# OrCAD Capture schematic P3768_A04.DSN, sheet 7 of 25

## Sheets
7 0018_CAMERA: size Custom
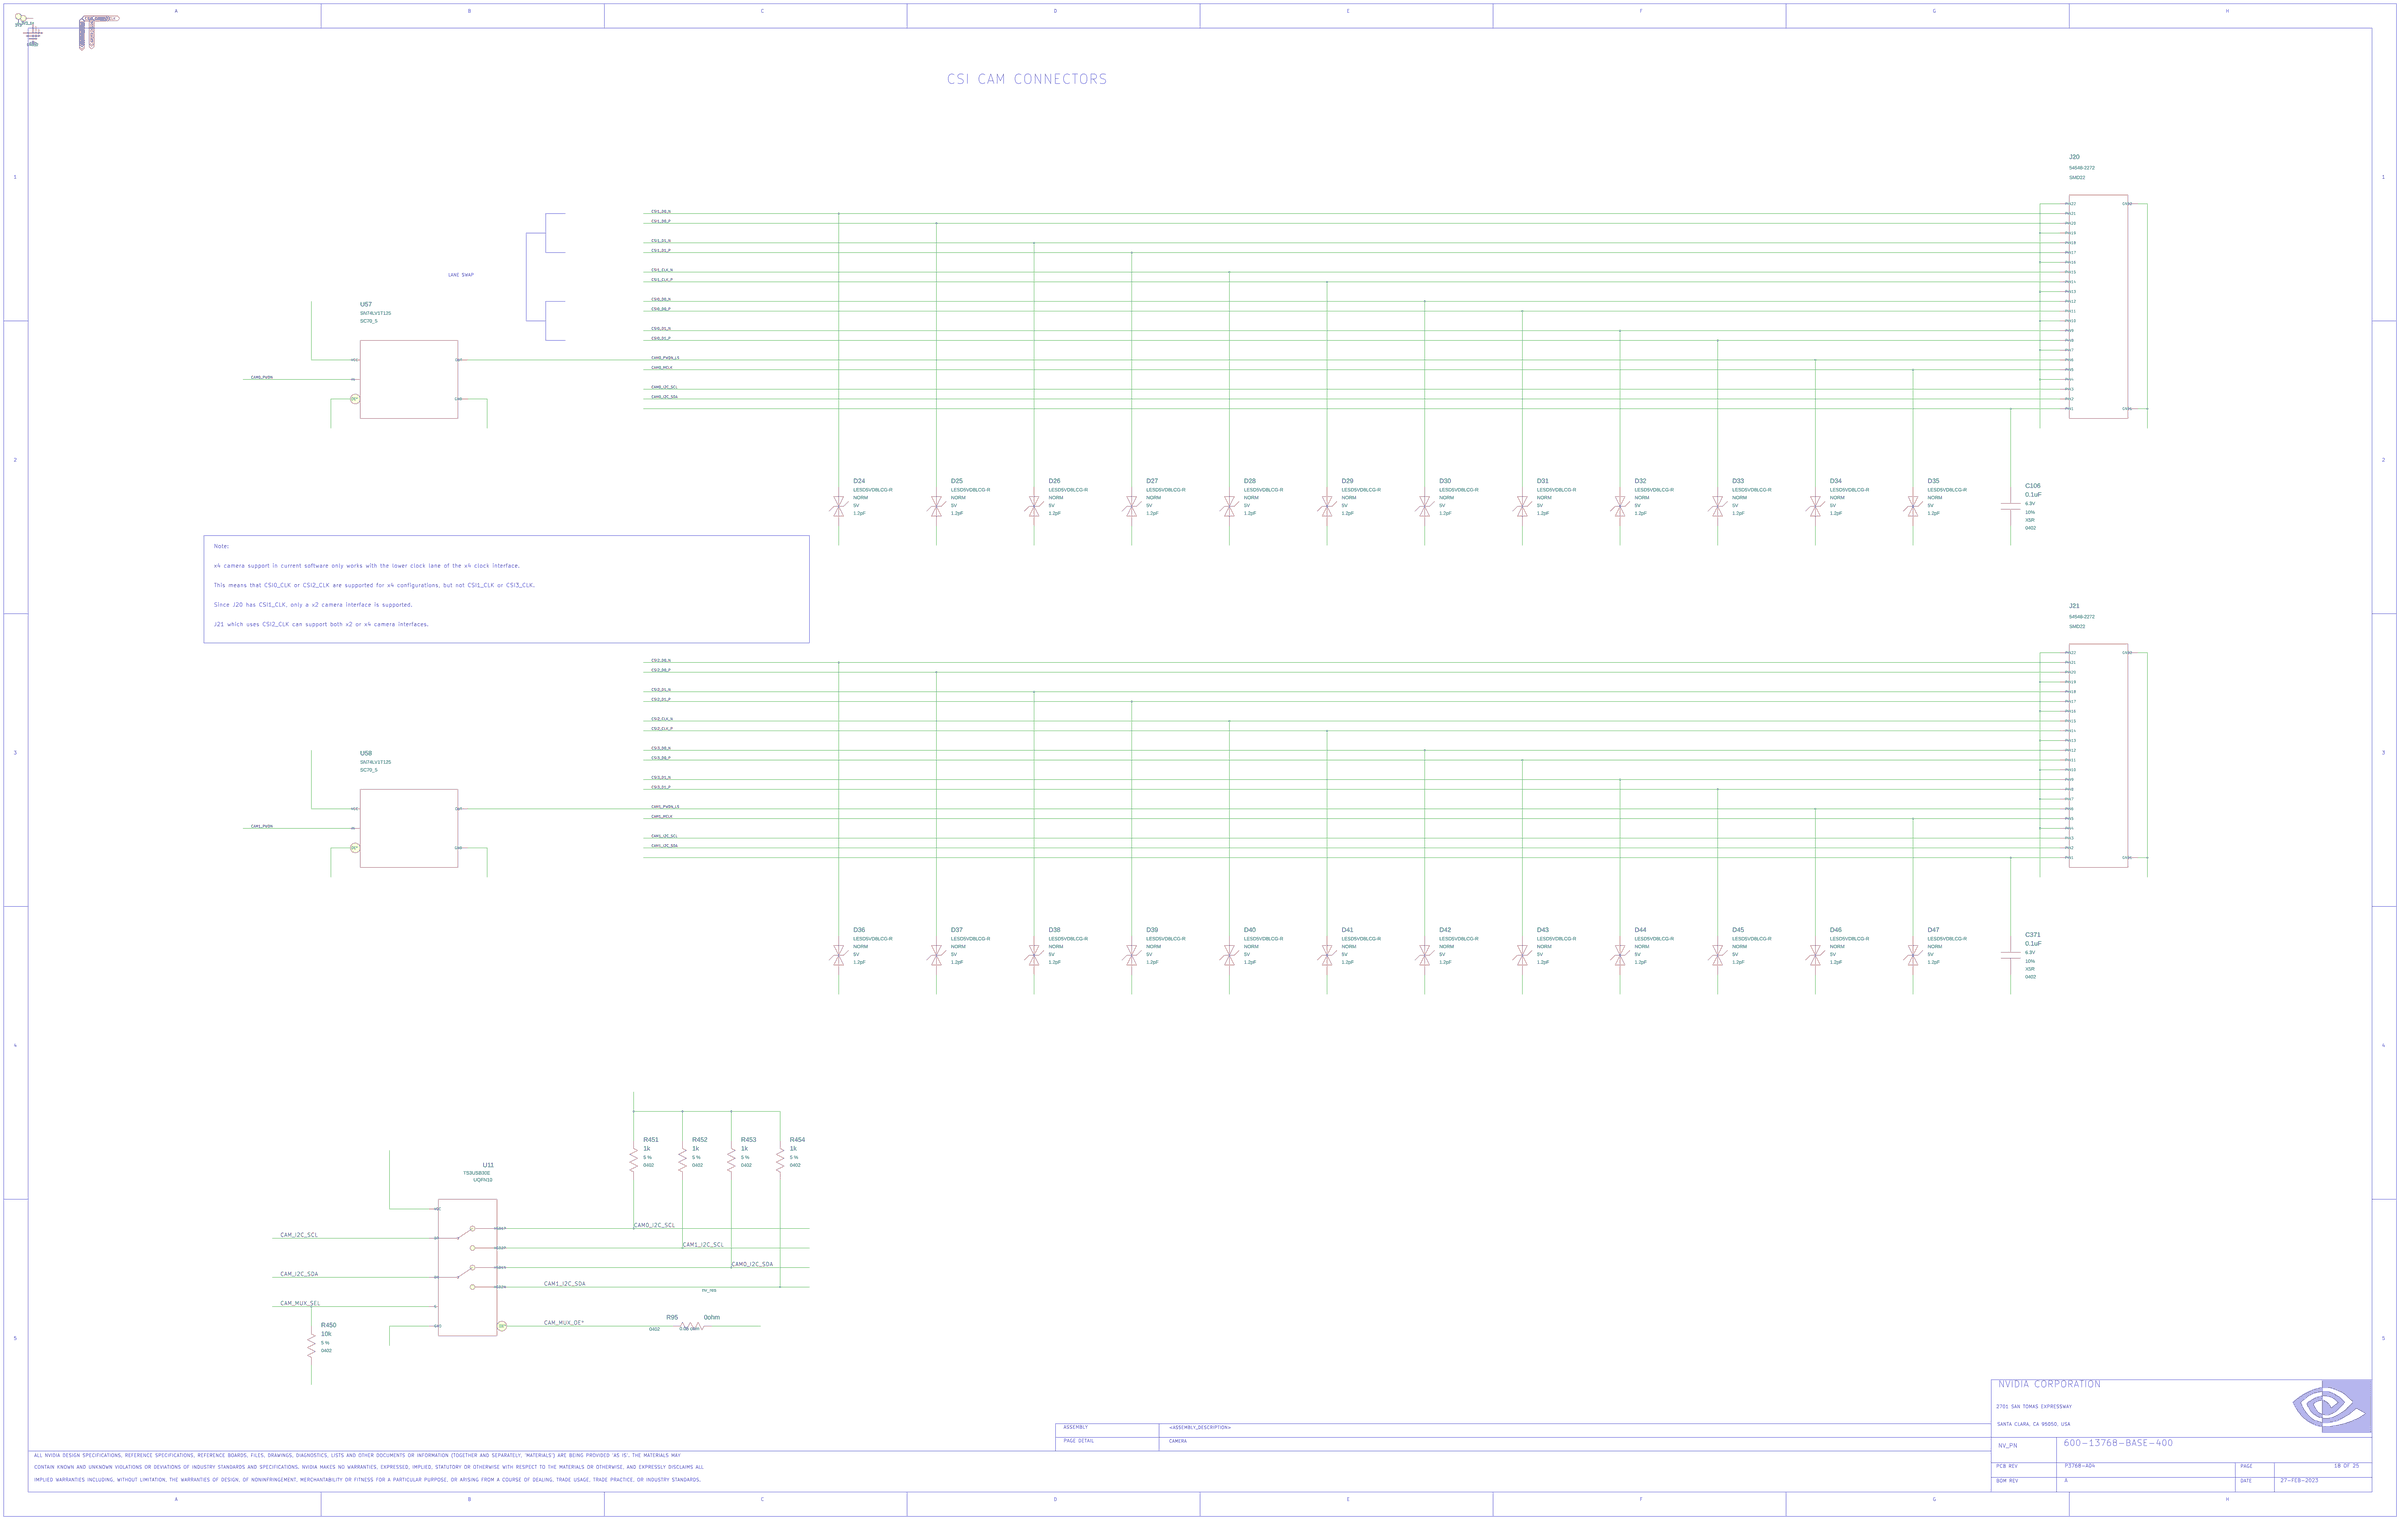
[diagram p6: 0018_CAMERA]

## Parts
C106  0.1uF  [0402]
C371  0.1uF  [0402]
D24  D_ESD  [DIODE_SMD_010X006_B]
D25  D_ESD  [DIODE_SMD_010X006_B]
D26  D_ESD  [DIODE_SMD_010X006_B]
D27  D_ESD  [DIODE_SMD_010X006_B]
D28  D_ESD  [DIODE_SMD_010X006_B]
D29  D_ESD  [DIODE_SMD_010X006_B]
D30  D_ESD  [DIODE_SMD_010X006_B]
D31  D_ESD  [DIODE_SMD_010X006_B]
D32  D_ESD  [DIODE_SMD_010X006_B]
D33  D_ESD  [DIODE_SMD_010X006_B]
D34  D_ESD  [DIODE_SMD_010X006_B]
D35  D_ESD  [DIODE_SMD_010X006_B]
D36  D_ESD  [DIODE_SMD_010X006_B]
D37  D_ESD  [DIODE_SMD_010X006_B]
D38  D_ESD  [DIODE_SMD_010X006_B]
D39  D_ESD  [DIODE_SMD_010X006_B]
D40  D_ESD  [DIODE_SMD_010X006_B]
D41  D_ESD  [DIODE_SMD_010X006_B]
D42  D_ESD  [DIODE_SMD_010X006_B]
D43  D_ESD  [DIODE_SMD_010X006_B]
D44  D_ESD  [DIODE_SMD_010X006_B]
D45  D_ESD  [DIODE_SMD_010X006_B]
D46  D_ESD  [DIODE_SMD_010X006_B]
D47  D_ESD  [DIODE_SMD_010X006_B]
J20  CON_FPC_22  [CON_FFC_022_SMD_F_RA_P050_ZIF]
J21  CON_FPC_22  [CON_FFC_022_SMD_F_RA_P050_ZIF]
R95  0ohm  [0402]
R450  10k  [0402]
R451  1k  [0402]
R452  1k  [0402]
R453  1k  [0402]
R454  1k  [0402]
U11  U_SW_ANA_USB  [QFN010R_P040_0018X0014]
U57  U_LEVSHFT_3STATE  [SC70_5]
U58  U_LEVSHFT_3STATE  [SC70_5]

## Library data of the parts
C106 = C#1: ASSEMBLY: CAM; CDS_LIB: discrete; CDS_PART_NAME: C_0402-0.1UF,X5R,10%,6.3V,039-0007-000; CDS_PHYS_PART_NAME: C_0402-0.1UF,X5R,10%,6.3V,039-0007-000-0.1UF,039-0007-000; CDS_SEC: 1; CHIPS_PART_NAME: C; DEVICE_TYPENAME: C_0402-01UFX5R1063V039-0007-000-01UF039-0007-000; DRAWING: @P3768_A04_LIB.P3768_A04(SCH_1):PAGE18; ESL: N/A; ESR: N/A; MAT: X5R; MAX_VOLTAGE: 6.3V; NV_PN: 039-0007-000; PATH: I182; PHYS_PAGE: 18; PSPICETEMPLATE: X^@REFDES  %1    %2   @NV_PN; ROT: 0; SEC: 1; SIGNAL_MODEL: nv_cap; TOL: 10%; VER: 1; XY: (-1850,5050)
C371 = C#1: ASSEMBLY: CAM; CDS_LIB: discrete; CDS_PART_NAME: C_0402-0.1UF,X5R,10%,6.3V,039-0007-000; CDS_PHYS_PART_NAME: C_0402-0.1UF,X5R,10%,6.3V,039-0007-000-0.1UF,039-0007-000; CDS_SEC: 1; CHIPS_PART_NAME: C; DEVICE_TYPENAME: C_0402-01UFX5R1063V039-0007-000-01UF039-0007-000; DRAWING: @P3768_A04_LIB.P3768_A04(SCH_1):PAGE18; ESL: N/A; ESR: N/A; MAT: X5R; MAX_VOLTAGE: 6.3V; NV_PN: 039-0007-000; PATH: I255; PHYS_PAGE: 18; PSPICETEMPLATE: X^@REFDES  %1    %2   @NV_PN; ROT: 0; SEC: 1; SIGNAL_MODEL: nv_cap; TOL: 10%; VER: 1; XY: (-1850,2750)
D24 = D_ESD: ASSEMBLY: CAM; BREAKDOWN_VOLTAGE_MIN_TYP: 5.5V; CAPACITANCE_MAX_TYP: 1.2pF; CDS_LIB: discrete; CDS_PART_NAME: D_ESD_NORM-LESD5VD8LCG-R,1 LINE,BI-DIRECTIONAL,5V,0.05UA,5.5V,10V@2A,1.2PF,090-0172-000; CDS_PHYS_PART_NAME: D_ESD_NORM-LESD5VD8LCG-R,1 LINE,BI-DIRECTIONAL,5V,0.05UA,5.5V,10V@2A,1.2PF,090-0172-000-090-0172-000; CDS_SEC: 1; CLAMPING_VOLTAGE: 10V@2A; CONFIGURATION: 1 Line; DEVICE_TYPENAME: D_ESD_NORM-LESD5VD8LCG-R1LINEBI-DIRECTIONAL5V005UA55V10V2A12PF090-0172-000-090-0172-000; DRAWING: @P3768_A04_LIB.P3768_A04(SCH_1):PAGE18; MAX_REVERSE_LEAKAGE_CURRENT: 0.05uA; MAX_REVERSE_VOLTAGE: 5V; NV_NAME: LESD5VD8LCG-R; NV_PN: 090-0172-000; PACK_TYPE: NORM; PATH: I211; PHYS_PAGE: 18; POLARITY: Bi-Directional; ROT: 0; SEC: 1; VER: 2; XY: (-7850,5050)
D25 = D_ESD: ASSEMBLY: CAM; BREAKDOWN_VOLTAGE_MIN_TYP: 5.5V; CAPACITANCE_MAX_TYP: 1.2pF; CDS_LIB: discrete; CDS_PART_NAME: D_ESD_NORM-LESD5VD8LCG-R,1 LINE,BI-DIRECTIONAL,5V,0.05UA,5.5V,10V@2A,1.2PF,090-0172-000; CDS_PHYS_PART_NAME: D_ESD_NORM-LESD5VD8LCG-R,1 LINE,BI-DIRECTIONAL,5V,0.05UA,5.5V,10V@2A,1.2PF,090-0172-000-090-0172-000; CDS_SEC: 1; CLAMPING_VOLTAGE: 10V@2A; CONFIGURATION: 1 Line; DEVICE_TYPENAME: D_ESD_NORM-LESD5VD8LCG-R1LINEBI-DIRECTIONAL5V005UA55V10V2A12PF090-0172-000-090-0172-000; DRAWING: @P3768_A04_LIB.P3768_A04(SCH_1):PAGE18; MAX_REVERSE_LEAKAGE_CURRENT: 0.05uA; MAX_REVERSE_VOLTAGE: 5V; NV_NAME: LESD5VD8LCG-R; NV_PN: 090-0172-000; PACK_TYPE: NORM; PATH: I208; PHYS_PAGE: 18; POLARITY: Bi-Directional; ROT: 0; SEC: 1; VER: 2; XY: (-7350,5050)
D26 = D_ESD: ASSEMBLY: CAM; BREAKDOWN_VOLTAGE_MIN_TYP: 5.5V; CAPACITANCE_MAX_TYP: 1.2pF; CDS_LIB: discrete; CDS_PART_NAME: D_ESD_NORM-LESD5VD8LCG-R,1 LINE,BI-DIRECTIONAL,5V,0.05UA,5.5V,10V@2A,1.2PF,090-0172-000; CDS_PHYS_PART_NAME: D_ESD_NORM-LESD5VD8LCG-R,1 LINE,BI-DIRECTIONAL,5V,0.05UA,5.5V,10V@2A,1.2PF,090-0172-000-090-0172-000; CDS_SEC: 1; CLAMPING_VOLTAGE: 10V@2A; CONFIGURATION: 1 Line; DEVICE_TYPENAME: D_ESD_NORM-LESD5VD8LCG-R1LINEBI-DIRECTIONAL5V005UA55V10V2A12PF090-0172-000-090-0172-000; DRAWING: @P3768_A04_LIB.P3768_A04(SCH_1):PAGE18; MAX_REVERSE_LEAKAGE_CURRENT: 0.05uA; MAX_REVERSE_VOLTAGE: 5V; NV_NAME: LESD5VD8LCG-R; NV_PN: 090-0172-000; PACK_TYPE: NORM; PATH: I206; PHYS_PAGE: 18; POLARITY: Bi-Directional; ROT: 0; SEC: 1; VER: 2; XY: (-6850,5050)
D27 = D_ESD: ASSEMBLY: CAM; BREAKDOWN_VOLTAGE_MIN_TYP: 5.5V; CAPACITANCE_MAX_TYP: 1.2pF; CDS_LIB: discrete; CDS_PART_NAME: D_ESD_NORM-LESD5VD8LCG-R,1 LINE,BI-DIRECTIONAL,5V,0.05UA,5.5V,10V@2A,1.2PF,090-0172-000; CDS_PHYS_PART_NAME: D_ESD_NORM-LESD5VD8LCG-R,1 LINE,BI-DIRECTIONAL,5V,0.05UA,5.5V,10V@2A,1.2PF,090-0172-000-090-0172-000; CDS_SEC: 1; CLAMPING_VOLTAGE: 10V@2A; CONFIGURATION: 1 Line; DEVICE_TYPENAME: D_ESD_NORM-LESD5VD8LCG-R1LINEBI-DIRECTIONAL5V005UA55V10V2A12PF090-0172-000-090-0172-000; DRAWING: @P3768_A04_LIB.P3768_A04(SCH_1):PAGE18; MAX_REVERSE_LEAKAGE_CURRENT: 0.05uA; MAX_REVERSE_VOLTAGE: 5V; NV_NAME: LESD5VD8LCG-R; NV_PN: 090-0172-000; PACK_TYPE: NORM; PATH: I204; PHYS_PAGE: 18; POLARITY: Bi-Directional; ROT: 0; SEC: 1; VER: 2; XY: (-6350,5050)
D28 = D_ESD: ASSEMBLY: CAM; BREAKDOWN_VOLTAGE_MIN_TYP: 5.5V; CAPACITANCE_MAX_TYP: 1.2pF; CDS_LIB: discrete; CDS_PART_NAME: D_ESD_NORM-LESD5VD8LCG-R,1 LINE,BI-DIRECTIONAL,5V,0.05UA,5.5V,10V@2A,1.2PF,090-0172-000; CDS_PHYS_PART_NAME: D_ESD_NORM-LESD5VD8LCG-R,1 LINE,BI-DIRECTIONAL,5V,0.05UA,5.5V,10V@2A,1.2PF,090-0172-000-090-0172-000; CDS_SEC: 1; CLAMPING_VOLTAGE: 10V@2A; CONFIGURATION: 1 Line; DEVICE_TYPENAME: D_ESD_NORM-LESD5VD8LCG-R1LINEBI-DIRECTIONAL5V005UA55V10V2A12PF090-0172-000-090-0172-000; DRAWING: @P3768_A04_LIB.P3768_A04(SCH_1):PAGE18; MAX_REVERSE_LEAKAGE_CURRENT: 0.05uA; MAX_REVERSE_VOLTAGE: 5V; NV_NAME: LESD5VD8LCG-R; NV_PN: 090-0172-000; PACK_TYPE: NORM; PATH: I202; PHYS_PAGE: 18; POLARITY: Bi-Directional; ROT: 0; SEC: 1; VER: 2; XY: (-5850,5050)
D29 = D_ESD: ASSEMBLY: CAM; BREAKDOWN_VOLTAGE_MIN_TYP: 5.5V; CAPACITANCE_MAX_TYP: 1.2pF; CDS_LIB: discrete; CDS_PART_NAME: D_ESD_NORM-LESD5VD8LCG-R,1 LINE,BI-DIRECTIONAL,5V,0.05UA,5.5V,10V@2A,1.2PF,090-0172-000; CDS_PHYS_PART_NAME: D_ESD_NORM-LESD5VD8LCG-R,1 LINE,BI-DIRECTIONAL,5V,0.05UA,5.5V,10V@2A,1.2PF,090-0172-000-090-0172-000; CDS_SEC: 1; CLAMPING_VOLTAGE: 10V@2A; CONFIGURATION: 1 Line; DEVICE_TYPENAME: D_ESD_NORM-LESD5VD8LCG-R1LINEBI-DIRECTIONAL5V005UA55V10V2A12PF090-0172-000-090-0172-000; DRAWING: @P3768_A04_LIB.P3768_A04(SCH_1):PAGE18; MAX_REVERSE_LEAKAGE_CURRENT: 0.05uA; MAX_REVERSE_VOLTAGE: 5V; NV_NAME: LESD5VD8LCG-R; NV_PN: 090-0172-000; PACK_TYPE: NORM; PATH: I200; PHYS_PAGE: 18; POLARITY: Bi-Directional; ROT: 0; SEC: 1; VER: 2; XY: (-5350,5050)
D30 = D_ESD: ASSEMBLY: CAM; BREAKDOWN_VOLTAGE_MIN_TYP: 5.5V; CAPACITANCE_MAX_TYP: 1.2pF; CDS_LIB: discrete; CDS_PART_NAME: D_ESD_NORM-LESD5VD8LCG-R,1 LINE,BI-DIRECTIONAL,5V,0.05UA,5.5V,10V@2A,1.2PF,090-0172-000; CDS_PHYS_PART_NAME: D_ESD_NORM-LESD5VD8LCG-R,1 LINE,BI-DIRECTIONAL,5V,0.05UA,5.5V,10V@2A,1.2PF,090-0172-000-090-0172-000; CDS_SEC: 1; CLAMPING_VOLTAGE: 10V@2A; CONFIGURATION: 1 Line; DEVICE_TYPENAME: D_ESD_NORM-LESD5VD8LCG-R1LINEBI-DIRECTIONAL5V005UA55V10V2A12PF090-0172-000-090-0172-000; DRAWING: @P3768_A04_LIB.P3768_A04(SCH_1):PAGE18; MAX_REVERSE_LEAKAGE_CURRENT: 0.05uA; MAX_REVERSE_VOLTAGE: 5V; NV_NAME: LESD5VD8LCG-R; NV_PN: 090-0172-000; PACK_TYPE: NORM; PATH: I191; PHYS_PAGE: 18; POLARITY: Bi-Directional; ROT: 0; SEC: 1; VER: 2; XY: (-4850,5050)
D31 = D_ESD: ASSEMBLY: CAM; BREAKDOWN_VOLTAGE_MIN_TYP: 5.5V; CAPACITANCE_MAX_TYP: 1.2pF; CDS_LIB: discrete; CDS_PART_NAME: D_ESD_NORM-LESD5VD8LCG-R,1 LINE,BI-DIRECTIONAL,5V,0.05UA,5.5V,10V@2A,1.2PF,090-0172-000; CDS_PHYS_PART_NAME: D_ESD_NORM-LESD5VD8LCG-R,1 LINE,BI-DIRECTIONAL,5V,0.05UA,5.5V,10V@2A,1.2PF,090-0172-000-090-0172-000; CDS_SEC: 1; CLAMPING_VOLTAGE: 10V@2A; CONFIGURATION: 1 Line; DEVICE_TYPENAME: D_ESD_NORM-LESD5VD8LCG-R1LINEBI-DIRECTIONAL5V005UA55V10V2A12PF090-0172-000-090-0172-000; DRAWING: @P3768_A04_LIB.P3768_A04(SCH_1):PAGE18; MAX_REVERSE_LEAKAGE_CURRENT: 0.05uA; MAX_REVERSE_VOLTAGE: 5V; NV_NAME: LESD5VD8LCG-R; NV_PN: 090-0172-000; PACK_TYPE: NORM; PATH: I189; PHYS_PAGE: 18; POLARITY: Bi-Directional; ROT: 0; SEC: 1; VER: 2; XY: (-4350,5050)
D32 = D_ESD: ASSEMBLY: CAM; BREAKDOWN_VOLTAGE_MIN_TYP: 5.5V; CAPACITANCE_MAX_TYP: 1.2pF; CDS_LIB: discrete; CDS_PART_NAME: D_ESD_NORM-LESD5VD8LCG-R,1 LINE,BI-DIRECTIONAL,5V,0.05UA,5.5V,10V@2A,1.2PF,090-0172-000; CDS_PHYS_PART_NAME: D_ESD_NORM-LESD5VD8LCG-R,1 LINE,BI-DIRECTIONAL,5V,0.05UA,5.5V,10V@2A,1.2PF,090-0172-000-090-0172-000; CDS_SEC: 1; CLAMPING_VOLTAGE: 10V@2A; CONFIGURATION: 1 Line; DEVICE_TYPENAME: D_ESD_NORM-LESD5VD8LCG-R1LINEBI-DIRECTIONAL5V005UA55V10V2A12PF090-0172-000-090-0172-000; DRAWING: @P3768_A04_LIB.P3768_A04(SCH_1):PAGE18; MAX_REVERSE_LEAKAGE_CURRENT: 0.05uA; MAX_REVERSE_VOLTAGE: 5V; NV_NAME: LESD5VD8LCG-R; NV_PN: 090-0172-000; PACK_TYPE: NORM; PATH: I187; PHYS_PAGE: 18; POLARITY: Bi-Directional; ROT: 0; SEC: 1; VER: 2; XY: (-3850,5050)
D33 = D_ESD: ASSEMBLY: CAM; BREAKDOWN_VOLTAGE_MIN_TYP: 5.5V; CAPACITANCE_MAX_TYP: 1.2pF; CDS_LIB: discrete; CDS_PART_NAME: D_ESD_NORM-LESD5VD8LCG-R,1 LINE,BI-DIRECTIONAL,5V,0.05UA,5.5V,10V@2A,1.2PF,090-0172-000; CDS_PHYS_PART_NAME: D_ESD_NORM-LESD5VD8LCG-R,1 LINE,BI-DIRECTIONAL,5V,0.05UA,5.5V,10V@2A,1.2PF,090-0172-000-090-0172-000; CDS_SEC: 1; CLAMPING_VOLTAGE: 10V@2A; CONFIGURATION: 1 Line; DEVICE_TYPENAME: D_ESD_NORM-LESD5VD8LCG-R1LINEBI-DIRECTIONAL5V005UA55V10V2A12PF090-0172-000-090-0172-000; DRAWING: @P3768_A04_LIB.P3768_A04(SCH_1):PAGE18; MAX_REVERSE_LEAKAGE_CURRENT: 0.05uA; MAX_REVERSE_VOLTAGE: 5V; NV_NAME: LESD5VD8LCG-R; NV_PN: 090-0172-000; PACK_TYPE: NORM; PATH: I185; PHYS_PAGE: 18; POLARITY: Bi-Directional; ROT: 0; SEC: 1; VER: 2; XY: (-3350,5050)
D34 = D_ESD: ASSEMBLY: CAM; BREAKDOWN_VOLTAGE_MIN_TYP: 5.5V; CAPACITANCE_MAX_TYP: 1.2pF; CDS_LIB: discrete; CDS_PART_NAME: D_ESD_NORM-LESD5VD8LCG-R,1 LINE,BI-DIRECTIONAL,5V,0.05UA,5.5V,10V@2A,1.2PF,090-0172-000; CDS_PHYS_PART_NAME: D_ESD_NORM-LESD5VD8LCG-R,1 LINE,BI-DIRECTIONAL,5V,0.05UA,5.5V,10V@2A,1.2PF,090-0172-000-090-0172-000; CDS_SEC: 1; CLAMPING_VOLTAGE: 10V@2A; CONFIGURATION: 1 Line; DEVICE_TYPENAME: D_ESD_NORM-LESD5VD8LCG-R1LINEBI-DIRECTIONAL5V005UA55V10V2A12PF090-0172-000-090-0172-000; DRAWING: @P3768_A04_LIB.P3768_A04(SCH_1):PAGE18; MAX_REVERSE_LEAKAGE_CURRENT: 0.05uA; MAX_REVERSE_VOLTAGE: 5V; NV_NAME: LESD5VD8LCG-R; NV_PN: 090-0172-000; PACK_TYPE: NORM; PATH: I175; PHYS_PAGE: 18; POLARITY: Bi-Directional; ROT: 0; SEC: 1; VER: 2; XY: (-2850,5050)
D35 = D_ESD: ASSEMBLY: CAM; BREAKDOWN_VOLTAGE_MIN_TYP: 5.5V; CAPACITANCE_MAX_TYP: 1.2pF; CDS_LIB: discrete; CDS_PART_NAME: D_ESD_NORM-LESD5VD8LCG-R,1 LINE,BI-DIRECTIONAL,5V,0.05UA,5.5V,10V@2A,1.2PF,090-0172-000; CDS_PHYS_PART_NAME: D_ESD_NORM-LESD5VD8LCG-R,1 LINE,BI-DIRECTIONAL,5V,0.05UA,5.5V,10V@2A,1.2PF,090-0172-000-090-0172-000; CDS_SEC: 1; CLAMPING_VOLTAGE: 10V@2A; CONFIGURATION: 1 Line; DEVICE_TYPENAME: D_ESD_NORM-LESD5VD8LCG-R1LINEBI-DIRECTIONAL5V005UA55V10V2A12PF090-0172-000-090-0172-000; DRAWING: @P3768_A04_LIB.P3768_A04(SCH_1):PAGE18; MAX_REVERSE_LEAKAGE_CURRENT: 0.05uA; MAX_REVERSE_VOLTAGE: 5V; NV_NAME: LESD5VD8LCG-R; NV_PN: 090-0172-000; PACK_TYPE: NORM; PATH: I173; PHYS_PAGE: 18; POLARITY: Bi-Directional; ROT: 0; SEC: 1; VER: 2; XY: (-2350,5050)
D36 = D_ESD: ASSEMBLY: CAM; BREAKDOWN_VOLTAGE_MIN_TYP: 5.5V; CAPACITANCE_MAX_TYP: 1.2pF; CDS_LIB: discrete; CDS_PART_NAME: D_ESD_NORM-LESD5VD8LCG-R,1 LINE,BI-DIRECTIONAL,5V,0.05UA,5.5V,10V@2A,1.2PF,090-0172-000; CDS_PHYS_PART_NAME: D_ESD_NORM-LESD5VD8LCG-R,1 LINE,BI-DIRECTIONAL,5V,0.05UA,5.5V,10V@2A,1.2PF,090-0172-000-090-0172-000; CDS_SEC: 1; CLAMPING_VOLTAGE: 10V@2A; CONFIGURATION: 1 Line; DEVICE_TYPENAME: D_ESD_NORM-LESD5VD8LCG-R1LINEBI-DIRECTIONAL5V005UA55V10V2A12PF090-0172-000-090-0172-000; DRAWING: @P3768_A04_LIB.P3768_A04(SCH_1):PAGE18; MAX_REVERSE_LEAKAGE_CURRENT: 0.05uA; MAX_REVERSE_VOLTAGE: 5V; NV_NAME: LESD5VD8LCG-R; NV_PN: 090-0172-000; PACK_TYPE: NORM; PATH: I240; PHYS_PAGE: 18; POLARITY: Bi-Directional; ROT: 0; SEC: 1; VER: 2; XY: (-7850,2750)
D37 = D_ESD: ASSEMBLY: CAM; BREAKDOWN_VOLTAGE_MIN_TYP: 5.5V; CAPACITANCE_MAX_TYP: 1.2pF; CDS_LIB: discrete; CDS_PART_NAME: D_ESD_NORM-LESD5VD8LCG-R,1 LINE,BI-DIRECTIONAL,5V,0.05UA,5.5V,10V@2A,1.2PF,090-0172-000; CDS_PHYS_PART_NAME: D_ESD_NORM-LESD5VD8LCG-R,1 LINE,BI-DIRECTIONAL,5V,0.05UA,5.5V,10V@2A,1.2PF,090-0172-000-090-0172-000; CDS_SEC: 1; CLAMPING_VOLTAGE: 10V@2A; CONFIGURATION: 1 Line; DEVICE_TYPENAME: D_ESD_NORM-LESD5VD8LCG-R1LINEBI-DIRECTIONAL5V005UA55V10V2A12PF090-0172-000-090-0172-000; DRAWING: @P3768_A04_LIB.P3768_A04(SCH_1):PAGE18; MAX_REVERSE_LEAKAGE_CURRENT: 0.05uA; MAX_REVERSE_VOLTAGE: 5V; NV_NAME: LESD5VD8LCG-R; NV_PN: 090-0172-000; PACK_TYPE: NORM; PATH: I238; PHYS_PAGE: 18; POLARITY: Bi-Directional; ROT: 0; SEC: 1; VER: 2; XY: (-7350,2750)
D38 = D_ESD: ASSEMBLY: CAM; BREAKDOWN_VOLTAGE_MIN_TYP: 5.5V; CAPACITANCE_MAX_TYP: 1.2pF; CDS_LIB: discrete; CDS_PART_NAME: D_ESD_NORM-LESD5VD8LCG-R,1 LINE,BI-DIRECTIONAL,5V,0.05UA,5.5V,10V@2A,1.2PF,090-0172-000; CDS_PHYS_PART_NAME: D_ESD_NORM-LESD5VD8LCG-R,1 LINE,BI-DIRECTIONAL,5V,0.05UA,5.5V,10V@2A,1.2PF,090-0172-000-090-0172-000; CDS_SEC: 1; CLAMPING_VOLTAGE: 10V@2A; CONFIGURATION: 1 Line; DEVICE_TYPENAME: D_ESD_NORM-LESD5VD8LCG-R1LINEBI-DIRECTIONAL5V005UA55V10V2A12PF090-0172-000-090-0172-000; DRAWING: @P3768_A04_LIB.P3768_A04(SCH_1):PAGE18; MAX_REVERSE_LEAKAGE_CURRENT: 0.05uA; MAX_REVERSE_VOLTAGE: 5V; NV_NAME: LESD5VD8LCG-R; NV_PN: 090-0172-000; PACK_TYPE: NORM; PATH: I234; PHYS_PAGE: 18; POLARITY: Bi-Directional; ROT: 0; SEC: 1; VER: 2; XY: (-6850,2750)
D39 = D_ESD: ASSEMBLY: CAM; BREAKDOWN_VOLTAGE_MIN_TYP: 5.5V; CAPACITANCE_MAX_TYP: 1.2pF; CDS_LIB: discrete; CDS_PART_NAME: D_ESD_NORM-LESD5VD8LCG-R,1 LINE,BI-DIRECTIONAL,5V,0.05UA,5.5V,10V@2A,1.2PF,090-0172-000; CDS_PHYS_PART_NAME: D_ESD_NORM-LESD5VD8LCG-R,1 LINE,BI-DIRECTIONAL,5V,0.05UA,5.5V,10V@2A,1.2PF,090-0172-000-090-0172-000; CDS_SEC: 1; CLAMPING_VOLTAGE: 10V@2A; CONFIGURATION: 1 Line; DEVICE_TYPENAME: D_ESD_NORM-LESD5VD8LCG-R1LINEBI-DIRECTIONAL5V005UA55V10V2A12PF090-0172-000-090-0172-000; DRAWING: @P3768_A04_LIB.P3768_A04(SCH_1):PAGE18; MAX_REVERSE_LEAKAGE_CURRENT: 0.05uA; MAX_REVERSE_VOLTAGE: 5V; NV_NAME: LESD5VD8LCG-R; NV_PN: 090-0172-000; PACK_TYPE: NORM; PATH: I232; PHYS_PAGE: 18; POLARITY: Bi-Directional; ROT: 0; SEC: 1; VER: 2; XY: (-6350,2750)
D40 = D_ESD: ASSEMBLY: CAM; BREAKDOWN_VOLTAGE_MIN_TYP: 5.5V; CAPACITANCE_MAX_TYP: 1.2pF; CDS_LIB: discrete; CDS_PART_NAME: D_ESD_NORM-LESD5VD8LCG-R,1 LINE,BI-DIRECTIONAL,5V,0.05UA,5.5V,10V@2A,1.2PF,090-0172-000; CDS_PHYS_PART_NAME: D_ESD_NORM-LESD5VD8LCG-R,1 LINE,BI-DIRECTIONAL,5V,0.05UA,5.5V,10V@2A,1.2PF,090-0172-000-090-0172-000; CDS_SEC: 1; CLAMPING_VOLTAGE: 10V@2A; CONFIGURATION: 1 Line; DEVICE_TYPENAME: D_ESD_NORM-LESD5VD8LCG-R1LINEBI-DIRECTIONAL5V005UA55V10V2A12PF090-0172-000-090-0172-000; DRAWING: @P3768_A04_LIB.P3768_A04(SCH_1):PAGE18; MAX_REVERSE_LEAKAGE_CURRENT: 0.05uA; MAX_REVERSE_VOLTAGE: 5V; NV_NAME: LESD5VD8LCG-R; NV_PN: 090-0172-000; PACK_TYPE: NORM; PATH: I230; PHYS_PAGE: 18; POLARITY: Bi-Directional; ROT: 0; SEC: 1; VER: 2; XY: (-5850,2750)
D41 = D_ESD: ASSEMBLY: CAM; BREAKDOWN_VOLTAGE_MIN_TYP: 5.5V; CAPACITANCE_MAX_TYP: 1.2pF; CDS_LIB: discrete; CDS_PART_NAME: D_ESD_NORM-LESD5VD8LCG-R,1 LINE,BI-DIRECTIONAL,5V,0.05UA,5.5V,10V@2A,1.2PF,090-0172-000; CDS_PHYS_PART_NAME: D_ESD_NORM-LESD5VD8LCG-R,1 LINE,BI-DIRECTIONAL,5V,0.05UA,5.5V,10V@2A,1.2PF,090-0172-000-090-0172-000; CDS_SEC: 1; CLAMPING_VOLTAGE: 10V@2A; CONFIGURATION: 1 Line; DEVICE_TYPENAME: D_ESD_NORM-LESD5VD8LCG-R1LINEBI-DIRECTIONAL5V005UA55V10V2A12PF090-0172-000-090-0172-000; DRAWING: @P3768_A04_LIB.P3768_A04(SCH_1):PAGE18; MAX_REVERSE_LEAKAGE_CURRENT: 0.05uA; MAX_REVERSE_VOLTAGE: 5V; NV_NAME: LESD5VD8LCG-R; NV_PN: 090-0172-000; PACK_TYPE: NORM; PATH: I228; PHYS_PAGE: 18; POLARITY: Bi-Directional; ROT: 0; SEC: 1; VER: 2; XY: (-5350,2750)
D42 = D_ESD: ASSEMBLY: CAM; BREAKDOWN_VOLTAGE_MIN_TYP: 5.5V; CAPACITANCE_MAX_TYP: 1.2pF; CDS_LIB: discrete; CDS_PART_NAME: D_ESD_NORM-LESD5VD8LCG-R,1 LINE,BI-DIRECTIONAL,5V,0.05UA,5.5V,10V@2A,1.2PF,090-0172-000; CDS_PHYS_PART_NAME: D_ESD_NORM-LESD5VD8LCG-R,1 LINE,BI-DIRECTIONAL,5V,0.05UA,5.5V,10V@2A,1.2PF,090-0172-000-090-0172-000; CDS_SEC: 1; CLAMPING_VOLTAGE: 10V@2A; CONFIGURATION: 1 Line; DEVICE_TYPENAME: D_ESD_NORM-LESD5VD8LCG-R1LINEBI-DIRECTIONAL5V005UA55V10V2A12PF090-0172-000-090-0172-000; DRAWING: @P3768_A04_LIB.P3768_A04(SCH_1):PAGE18; MAX_REVERSE_LEAKAGE_CURRENT: 0.05uA; MAX_REVERSE_VOLTAGE: 5V; NV_NAME: LESD5VD8LCG-R; NV_PN: 090-0172-000; PACK_TYPE: NORM; PATH: I226; PHYS_PAGE: 18; POLARITY: Bi-Directional; ROT: 0; SEC: 1; VER: 2; XY: (-4850,2750)
D43 = D_ESD: ASSEMBLY: CAM; BREAKDOWN_VOLTAGE_MIN_TYP: 5.5V; CAPACITANCE_MAX_TYP: 1.2pF; CDS_LIB: discrete; CDS_PART_NAME: D_ESD_NORM-LESD5VD8LCG-R,1 LINE,BI-DIRECTIONAL,5V,0.05UA,5.5V,10V@2A,1.2PF,090-0172-000; CDS_PHYS_PART_NAME: D_ESD_NORM-LESD5VD8LCG-R,1 LINE,BI-DIRECTIONAL,5V,0.05UA,5.5V,10V@2A,1.2PF,090-0172-000-090-0172-000; CDS_SEC: 1; CLAMPING_VOLTAGE: 10V@2A; CONFIGURATION: 1 Line; DEVICE_TYPENAME: D_ESD_NORM-LESD5VD8LCG-R1LINEBI-DIRECTIONAL5V005UA55V10V2A12PF090-0172-000-090-0172-000; DRAWING: @P3768_A04_LIB.P3768_A04(SCH_1):PAGE18; MAX_REVERSE_LEAKAGE_CURRENT: 0.05uA; MAX_REVERSE_VOLTAGE: 5V; NV_NAME: LESD5VD8LCG-R; NV_PN: 090-0172-000; PACK_TYPE: NORM; PATH: I224; PHYS_PAGE: 18; POLARITY: Bi-Directional; ROT: 0; SEC: 1; VER: 2; XY: (-4350,2750)
D44 = D_ESD: ASSEMBLY: CAM; BREAKDOWN_VOLTAGE_MIN_TYP: 5.5V; CAPACITANCE_MAX_TYP: 1.2pF; CDS_LIB: discrete; CDS_PART_NAME: D_ESD_NORM-LESD5VD8LCG-R,1 LINE,BI-DIRECTIONAL,5V,0.05UA,5.5V,10V@2A,1.2PF,090-0172-000; CDS_PHYS_PART_NAME: D_ESD_NORM-LESD5VD8LCG-R,1 LINE,BI-DIRECTIONAL,5V,0.05UA,5.5V,10V@2A,1.2PF,090-0172-000-090-0172-000; CDS_SEC: 1; CLAMPING_VOLTAGE: 10V@2A; CONFIGURATION: 1 Line; DEVICE_TYPENAME: D_ESD_NORM-LESD5VD8LCG-R1LINEBI-DIRECTIONAL5V005UA55V10V2A12PF090-0172-000-090-0172-000; DRAWING: @P3768_A04_LIB.P3768_A04(SCH_1):PAGE18; MAX_REVERSE_LEAKAGE_CURRENT: 0.05uA; MAX_REVERSE_VOLTAGE: 5V; NV_NAME: LESD5VD8LCG-R; NV_PN: 090-0172-000; PACK_TYPE: NORM; PATH: I222; PHYS_PAGE: 18; POLARITY: Bi-Directional; ROT: 0; SEC: 1; VER: 2; XY: (-3850,2750)
D45 = D_ESD: ASSEMBLY: CAM; BREAKDOWN_VOLTAGE_MIN_TYP: 5.5V; CAPACITANCE_MAX_TYP: 1.2pF; CDS_LIB: discrete; CDS_PART_NAME: D_ESD_NORM-LESD5VD8LCG-R,1 LINE,BI-DIRECTIONAL,5V,0.05UA,5.5V,10V@2A,1.2PF,090-0172-000; CDS_PHYS_PART_NAME: D_ESD_NORM-LESD5VD8LCG-R,1 LINE,BI-DIRECTIONAL,5V,0.05UA,5.5V,10V@2A,1.2PF,090-0172-000-090-0172-000; CDS_SEC: 1; CLAMPING_VOLTAGE: 10V@2A; CONFIGURATION: 1 Line; DEVICE_TYPENAME: D_ESD_NORM-LESD5VD8LCG-R1LINEBI-DIRECTIONAL5V005UA55V10V2A12PF090-0172-000-090-0172-000; DRAWING: @P3768_A04_LIB.P3768_A04(SCH_1):PAGE18; MAX_REVERSE_LEAKAGE_CURRENT: 0.05uA; MAX_REVERSE_VOLTAGE: 5V; NV_NAME: LESD5VD8LCG-R; NV_PN: 090-0172-000; PACK_TYPE: NORM; PATH: I220; PHYS_PAGE: 18; POLARITY: Bi-Directional; ROT: 0; SEC: 1; VER: 2; XY: (-3350,2750)
D46 = D_ESD: ASSEMBLY: CAM; BREAKDOWN_VOLTAGE_MIN_TYP: 5.5V; CAPACITANCE_MAX_TYP: 1.2pF; CDS_LIB: discrete; CDS_PART_NAME: D_ESD_NORM-LESD5VD8LCG-R,1 LINE,BI-DIRECTIONAL,5V,0.05UA,5.5V,10V@2A,1.2PF,090-0172-000; CDS_PHYS_PART_NAME: D_ESD_NORM-LESD5VD8LCG-R,1 LINE,BI-DIRECTIONAL,5V,0.05UA,5.5V,10V@2A,1.2PF,090-0172-000-090-0172-000; CDS_SEC: 1; CLAMPING_VOLTAGE: 10V@2A; CONFIGURATION: 1 Line; DEVICE_TYPENAME: D_ESD_NORM-LESD5VD8LCG-R1LINEBI-DIRECTIONAL5V005UA55V10V2A12PF090-0172-000-090-0172-000; DRAWING: @P3768_A04_LIB.P3768_A04(SCH_1):PAGE18; MAX_REVERSE_LEAKAGE_CURRENT: 0.05uA; MAX_REVERSE_VOLTAGE: 5V; NV_NAME: LESD5VD8LCG-R; NV_PN: 090-0172-000; PACK_TYPE: NORM; PATH: I218; PHYS_PAGE: 18; POLARITY: Bi-Directional; ROT: 0; SEC: 1; VER: 2; XY: (-2850,2750)
D47 = D_ESD: ASSEMBLY: CAM; BREAKDOWN_VOLTAGE_MIN_TYP: 5.5V; CAPACITANCE_MAX_TYP: 1.2pF; CDS_LIB: discrete; CDS_PART_NAME: D_ESD_NORM-LESD5VD8LCG-R,1 LINE,BI-DIRECTIONAL,5V,0.05UA,5.5V,10V@2A,1.2PF,090-0172-000; CDS_PHYS_PART_NAME: D_ESD_NORM-LESD5VD8LCG-R,1 LINE,BI-DIRECTIONAL,5V,0.05UA,5.5V,10V@2A,1.2PF,090-0172-000-090-0172-000; CDS_SEC: 1; CLAMPING_VOLTAGE: 10V@2A; CONFIGURATION: 1 Line; DEVICE_TYPENAME: D_ESD_NORM-LESD5VD8LCG-R1LINEBI-DIRECTIONAL5V005UA55V10V2A12PF090-0172-000-090-0172-000; DRAWING: @P3768_A04_LIB.P3768_A04(SCH_1):PAGE18; MAX_REVERSE_LEAKAGE_CURRENT: 0.05uA; MAX_REVERSE_VOLTAGE: 5V; NV_NAME: LESD5VD8LCG-R; NV_PN: 090-0172-000; PACK_TYPE: NORM; PATH: I216; PHYS_PAGE: 18; POLARITY: Bi-Directional; ROT: 0; SEC: 1; VER: 2; XY: (-2350,2750)
J20 = CON_FPC_22: ANGLE: 90; ASSEMBLY: CAM; CDS_LIB: electro_mechanic; CDS_PART_NAME: CON_FPC_22_SMD22-54548-2272,FEMALE,0.5MM,90,YES,YES,NO,NO,NO,50 V,0.5 A,080-2191-000; CDS_PHYS_PART_NAME: CON_FPC_22_SMD22-54548-2272,FEMALE,0.5MM,90,YES,YES,NO,NO,NO,50 V,0.5 A,080-2191-000-080-2191-000; CDS_SEC: 1; DEVICE_TYPENAME: CON_FPC_22_SMD22-54548-2272FEMALE05MM90YESYESNONONO50V05A080-2191-000-080-2191-000; DRAWING: @P3768_A04_LIB.P3768_A04(SCH_1):PAGE18; EMI_GROUND_TAB: No; GENDER: Female; LATCHING: NO; MAX_CURRENT: 0.5 A; MAX_VOLTAGE: 50 V; NV_NAME: 54548-2272; NV_PN: 080-2191-000; PACK_TYPE: SMD22; PATH: I320; PHYS_PAGE: 18; PITCH: 0.5mm; REFLOW: YES; ROT: 6; SEC: 1; SHIELDED: No; SHROUDED: YES; VER: 1; XY: (-1400,6050)
J21 = CON_FPC_22: ANGLE: 90; ASSEMBLY: CAM; CDS_LIB: electro_mechanic; CDS_PART_NAME: CON_FPC_22_SMD22-54548-2272,FEMALE,0.5MM,90,YES,YES,NO,NO,NO,50 V,0.5 A,080-2191-000; CDS_PHYS_PART_NAME: CON_FPC_22_SMD22-54548-2272,FEMALE,0.5MM,90,YES,YES,NO,NO,NO,50 V,0.5 A,080-2191-000-080-2191-000; CDS_SEC: 1; DEVICE_TYPENAME: CON_FPC_22_SMD22-54548-2272FEMALE05MM90YESYESNONONO50V05A080-2191-000-080-2191-000; DRAWING: @P3768_A04_LIB.P3768_A04(SCH_1):PAGE18; EMI_GROUND_TAB: No; GENDER: Female; LATCHING: NO; MAX_CURRENT: 0.5 A; MAX_VOLTAGE: 50 V; NV_NAME: 54548-2272; NV_PN: 080-2191-000; PACK_TYPE: SMD22; PATH: I319; PHYS_PAGE: 18; PITCH: 0.5mm; REFLOW: YES; ROT: 6; SEC: 1; SHIELDED: No; SHROUDED: YES; VER: 1; XY: (-1400,3750)
R95 = R#1: ASSEMBLY: CAM; CDS_LIB: discrete; CDS_PART_NAME: R_0402-0OHM,0.05 OHM,62.5MW,195-2655-000; CDS_PHYS_PART_NAME: R_0402-0OHM,0.05 OHM,62.5MW,195-2655-000-0OHM,195-2655-000; CDS_SEC: 1; CHIPS_PART_NAME: R; DEVICE_TYPENAME: R_0402-0OHM005OHM625MW195-2655-000-0OHM195-2655-000; DRAWING: @P3768_A04_LIB.P3768_A04(SCH_1):PAGE18; MAX_WATTAGE: 62.5mW; NV_PN: 195-2655-000; PATH: I264; PHYS_PAGE: 18; PSPICETEMPLATE: X^@REFDES  %1    %2   @NV_PN; ROT: 0; SEC: 1; SIGNAL_MODEL: nv_res; TOL: 0.05 ohm; VER: 1; XY: (-8600,850)
R450 = R: ASSEMBLY: CAM; CDS_LIB: discrete; CDS_PART_NAME: R_0402-10K,5 %,62.5MW,195-0486-000; CDS_PHYS_PART_NAME: R_0402-10K,5 %,62.5MW,195-0486-000-10K,195-0486-000; CDS_SEC: 1; DEVICE_TYPENAME: R_0402-10K5625MW195-0486-000-10K195-0486-000; DRAWING: @P3768_A04_LIB.P3768_A04(SCH_1):PAGE18; MAX_WATTAGE: 62.5mW; NV_PN: 195-0486-000; PATH: I271; PHYS_PAGE: 18; ROT: 0; SEC: 1; SIGNAL_MODEL: nv_res; TOL: 5 %; VER: 2; XY: (-10550,750)
R451 = R: ASSEMBLY: CAM; CDS_LIB: discrete; CDS_PART_NAME: R_0402-1K,5 %,62.5MW,195-0485-000; CDS_PHYS_PART_NAME: R_0402-1K,5 %,62.5MW,195-0485-000-195-0485-000,1K; CDS_SEC: 1; DEVICE_TYPENAME: R_0402-1K5625MW195-0485-000-195-0485-0001K; DRAWING: @P3768_A04_LIB.P3768_A04(SCH_1):PAGE18; MAX_WATTAGE: 62.5mW; NV_PN: 195-0485-000; PATH: I273; PHYS_PAGE: 18; ROT: 0; SEC: 1; SIGNAL_MODEL: nv_res; TOL: 5 %; VER: 2; XY: (-8900,1700)
R452 = R: ASSEMBLY: CAM; CDS_LIB: discrete; CDS_PART_NAME: R_0402-1K,5 %,62.5MW,195-0485-000; CDS_PHYS_PART_NAME: R_0402-1K,5 %,62.5MW,195-0485-000-195-0485-000,1K; CDS_SEC: 1; DEVICE_TYPENAME: R_0402-1K5625MW195-0485-000-195-0485-0001K; DRAWING: @P3768_A04_LIB.P3768_A04(SCH_1):PAGE18; MAX_WATTAGE: 62.5mW; NV_PN: 195-0485-000; PATH: I274; PHYS_PAGE: 18; ROT: 0; SEC: 1; SIGNAL_MODEL: nv_res; TOL: 5 %; VER: 2; XY: (-8650,1700)
R453 = R: ASSEMBLY: CAM; CDS_LIB: discrete; CDS_PART_NAME: R_0402-1K,5 %,62.5MW,195-0485-000; CDS_PHYS_PART_NAME: R_0402-1K,5 %,62.5MW,195-0485-000-195-0485-000,1K; CDS_SEC: 1; DEVICE_TYPENAME: R_0402-1K5625MW195-0485-000-195-0485-0001K; DRAWING: @P3768_A04_LIB.P3768_A04(SCH_1):PAGE18; MAX_WATTAGE: 62.5mW; NV_PN: 195-0485-000; PATH: I275; PHYS_PAGE: 18; ROT: 0; SEC: 1; SIGNAL_MODEL: nv_res; TOL: 5 %; VER: 2; XY: (-8400,1700)
R454 = R: ASSEMBLY: CAM; CDS_LIB: discrete; CDS_PART_NAME: R_0402-1K,5 %,62.5MW,195-0485-000; CDS_PHYS_PART_NAME: R_0402-1K,5 %,62.5MW,195-0485-000-195-0485-000,1K; CDS_SEC: 1; DEVICE_TYPENAME: R_0402-1K5625MW195-0485-000-195-0485-0001K; DRAWING: @P3768_A04_LIB.P3768_A04(SCH_1):PAGE18; MAX_WATTAGE: 62.5mW; NV_PN: 195-0485-000; PATH: I276; PHYS_PAGE: 18; ROT: 0; SEC: 1; SIGNAL_MODEL: nv_res; TOL: 5 %; VER: 2; XY: (-8150,1700)
U11 = U_SW_ANA_USB: ASSEMBLY: CAM; CDS_LIB: analog; CDS_PART_NAME: U_SW_ANA_USB_UQFN10-TS3USB30E,SWITCH - ANALOG,115-0655-000; CDS_PHYS_PART_NAME: U_SW_ANA_USB_UQFN10-TS3USB30E,SWITCH - ANALOG,115-0655-000-115-0655-000; CDS_SEC: 1; DEVICE_TYPENAME: U_SW_ANA_USB_UQFN10-TS3USB30ESWITCH-ANALOG115-0655-000-115-0655-000; DRAWING: @P3768_A04_LIB.P3768_A04(SCH_1):PAGE18; FUNCTION: Switch - Analog; NV_NAME: TS3USB30E; NV_PN: 115-0655-000; PACK_TYPE: UQFN10; PATH: I262; PHYS_PAGE: 18; ROT: 2; SEC: 1; VER: 3; XY: (-9750,1150)
U57 = U_LEVSHFT_3STATE: ASSEMBLY: CAM; CDS_LIB: logic; CDS_PART_NAME: U_LEVSHFT_3STATE_SC70_5-SN74LV1T125,LEVEL SHIFTER,115-2747-000; CDS_PHYS_PART_NAME: U_LEVSHFT_3STATE_SC70_5-SN74LV1T125,LEVEL SHIFTER,115-2747-000-115-2747-000; CDS_SEC: 1; DEVICE_TYPENAME: U_LEVSHFT_3STATE_SC70_5-SN74LV1T125LEVELSHIFTER115-2747-000-115-2747-000; DRAWING: @P3768_A04_LIB.P3768_A04(SCH_1):PAGE18; FUNCTION: Level Shifter; NV_NAME: SN74LV1T125; NV_PN: 115-2747-000; PATH: I313; PHYS_PAGE: 18; ROT: 0; SEC: 1; VER: 10; XY: (-10050,5700)
U58 = U_LEVSHFT_3STATE: ASSEMBLY: CAM; CDS_LIB: logic; CDS_PART_NAME: U_LEVSHFT_3STATE_SC70_5-SN74LV1T125,LEVEL SHIFTER,115-2747-000; CDS_PHYS_PART_NAME: U_LEVSHFT_3STATE_SC70_5-SN74LV1T125,LEVEL SHIFTER,115-2747-000-115-2747-000; CDS_SEC: 1; DEVICE_TYPENAME: U_LEVSHFT_3STATE_SC70_5-SN74LV1T125LEVELSHIFTER115-2747-000-115-2747-000; DRAWING: @P3768_A04_LIB.P3768_A04(SCH_1):PAGE18; FUNCTION: Level Shifter; NV_NAME: SN74LV1T125; NV_PN: 115-2747-000; PATH: I307; PHYS_PAGE: 18; ROT: 0; SEC: 1; VER: 10; XY: (-10050,3400)

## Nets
GND: C106.2 C371.2 D24.2 D25.2 D26.2 D27.2 D28.2 D29.2 D30.2 D31.2 D32.2 D33.2 D34.2 D35.2 D36.2 D37.2 D38.2 D39.2 D40.2 D41.2 D42.2 D43.2 D44.2 D45.2 D46.2 D47.2 J20.4(PIN4) J20.7(PIN7) J20.10(PIN10) J20.13(PIN13) J20.16(PIN16) J20.19(PIN19) J20.22(PIN22) J20.23(GND1) J20.24(GND2) J21.4(PIN4) J21.7(PIN7) J21.10(PIN10) J21.13(PIN13) J21.16(PIN16) J21.19(PIN19) J21.22(PIN22) J21.23(GND1) J21.24(GND2) R95.2 R450.2 U11.4(GND) U57.1(OE*) U57.3(GND) U58.1(OE*) U58.3(GND) ; also on sheet 1 2 3 4 5 6 8 9 10 11 12 13 14 15 16 17 18 19 21 25
VDD_3V3_SYS: C106.1 C371.1 J20.1(PIN1) J21.1(PIN1) R451.1 R452.1 R453.1 R454.1 U11.9(VCC) U57.5(VCC) U58.5(VCC) ; also on sheet 1 2 3 4 5 6 8 11 12 14 15 19 20 21
CAM0_I2C_SCL: J20.3(PIN3) R451.2 U11.1(HSD1P)
CAM0_I2C_SDA: J20.2(PIN2) R453.2 U11.7(HSD1N)
CAM0_MCLK: D35.1 J20.5(PIN5) ; also on sheet 20
CAM0_PWDN: U57.2(IN) ; also on sheet 20
CAM0_PWDN_LS: D34.1 J20.6(PIN6) U57.4(OUT)
CAM1_I2C_SCL: J21.3(PIN3) R452.2 U11.2(HSD2P)
CAM1_I2C_SDA: J21.2(PIN2) R454.2 U11.6(HSD2N)
CAM1_MCLK: D47.1 J21.5(PIN5) ; also on sheet 20
CAM1_PWDN: U58.2(IN) ; also on sheet 20
CAM1_PWDN_LS: D46.1 J21.6(PIN6) U58.4(OUT)
CAM_I2C_SCL: U11.3(DP) ; also on sheet 11 20
CAM_I2C_SDA: U11.5(DN) ; also on sheet 11 20
CAM_MUX_OE*: R95.1 U11.8(OE*)
CAM_MUX_SEL: R450.1 U11.10(S) ; also on sheet 20
CSI0_D0_N: D30.1 J20.12(PIN12) ; also on sheet 20
CSI0_D0_P: D31.1 J20.11(PIN11) ; also on sheet 20
CSI0_D1_N: D32.1 J20.9(PIN9) ; also on sheet 20
CSI0_D1_P: D33.1 J20.8(PIN8) ; also on sheet 20
CSI1_CLK_N: D28.1 J20.15(PIN15) ; also on sheet 20
CSI1_CLK_P: D29.1 J20.14(PIN14) ; also on sheet 20
CSI1_D0_N: D24.1 J20.21(PIN21) ; also on sheet 20
CSI1_D0_P: D25.1 J20.20(PIN20) ; also on sheet 20
CSI1_D1_N: D26.1 J20.18(PIN18) ; also on sheet 20
CSI1_D1_P: D27.1 J20.17(PIN17) ; also on sheet 20
CSI2_CLK_N: D40.1 J21.15(PIN15) ; also on sheet 20
CSI2_CLK_P: D41.1 J21.14(PIN14) ; also on sheet 20
CSI2_D0_N: D36.1 J21.21(PIN21) ; also on sheet 20
CSI2_D0_P: D37.1 J21.20(PIN20) ; also on sheet 20
CSI2_D1_N: D38.1 J21.18(PIN18) ; also on sheet 20
CSI2_D1_P: D39.1 J21.17(PIN17) ; also on sheet 20
CSI3_D0_N: D42.1 J21.12(PIN12) ; also on sheet 20
CSI3_D0_P: D43.1 J21.11(PIN11) ; also on sheet 20
CSI3_D1_N: D44.1 J21.9(PIN9) ; also on sheet 20
CSI3_D1_P: D45.1 J21.8(PIN8) ; also on sheet 20

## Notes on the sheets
sheet 7
- A
- B
- C
- D
- E
- F
- G
- H
- CSI CAM CONNECTORS
- 1
- 1
- LANE SWAP
- 2
- 2
- Note:
- x4 camera support in current software only works with the lower clock lane of the x4 clock interface.
- This means that CSI0_CLK or CSI2_CLK are supported for x4 configurations, but not CSI1_CLK or CSI3_CLK.
- Since J20 has CSI1_CLK, only a x2 camera interface is supported.
- J21 which uses CSI2_CLK can support both x2 or x4 camera interfaces.
- 3
- 3
- 4
- 4
- 5
- 5
- NVIDIA CORPORATION
- 2701 SAN TOMAS EXPRESSWAY
- SANTA CLARA, CA 95050, USA
- ASSEMBLY
- <ASSEMBLY_DESCRIPTION>
- PAGE DETAIL
- CAMERA
- 600-13768-BASE-400
- NV_PN
- ALL NVIDIA DESIGN SPECIFICATIONS, REFERENCE SPECIFICATIONS, REFERENCE BOARDS, FILES, DRAWINGS, DIAGNOSTICS, LISTS AND OTHER DOCUMENTS OR INFORMATION (TOGETHER AND SEPARATELY, 'MATERIALS') ARE BEING PROVIDED 'AS IS'. THE MATERIALS MAY
- P3768-A04
- 18 OF 25
- CONTAIN KNOWN AND UNKNOWN VIOLATIONS OR DEVIATIONS OF INDUSTRY STANDARDS AND SPECIFICATIONS. NVIDIA MAKES NO WARRANTIES, EXPRESSED, IMPLIED, STATUTORY OR OTHERWISE WITH RESPECT TO THE MATERIALS OR OTHERWISE, AND EXPRESSLY DISCLAIMS ALL
- PCB REV
- PAGE
- IMPLIED WARRANTIES INCLUDING, WITHOUT LIMITATION, THE WARRANTIES OF DESIGN, OF NONINFRINGEMENT, MERCHANTABILITY OR FITNESS FOR A PARTICULAR PURPOSE, OR ARISING FROM A COURSE OF DEALING, TRADE USAGE, TRADE PRACTICE, OR INDUSTRY STANDARDS.
- BOM REV
- A
- DATE
- 27-FEB-2023
- A
- B
- C
- D
- E
- F
- G
- H
